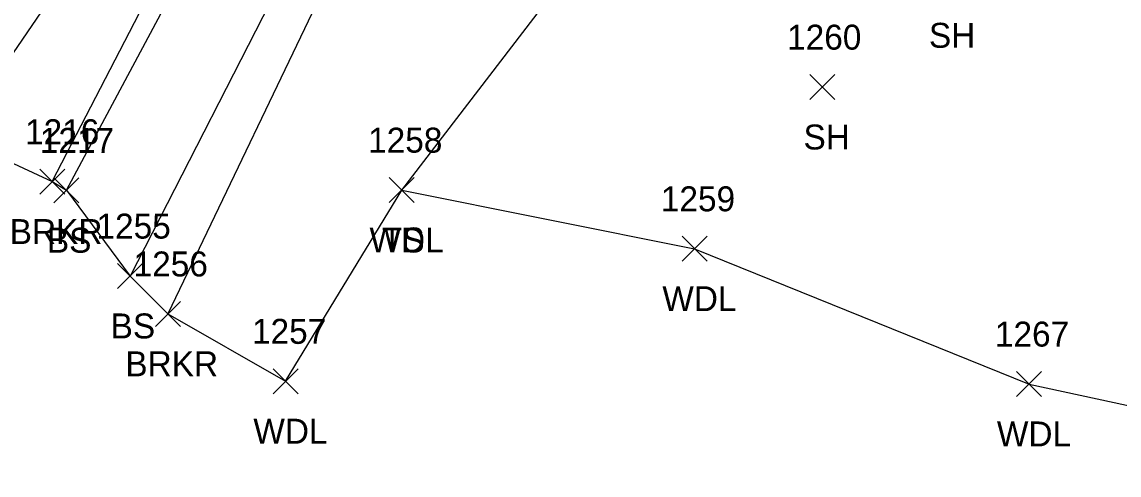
# Model space of a CAD drawing. Extents: x 1547013 to 1549434, y 267998 to 268739.
# Drawn here: x 1548511.9 to 1548599.8, y 268003.2 to 268039.5 of the extents above; entities that cross this region are included whole.
import ezdxf

# ---------------------------------------------------------------- set-up
doc = ezdxf.new("R2010")
doc.units = 0
for name, color, linetype in [('L_A', 7, 'Continuous'), ('L_I', 7, 'Continuous'), ('L_TIC', 7, 'Continuous'), ('LAWA', 7, 'Continuous'), ('LAWE', 7, 'Continuous'), ('LELB', 7, 'Continuous'), ('LSOGP', 7, 'Continuous')]:
    doc.layers.add(name, color=color, linetype=linetype)

msp = doc.modelspace()

# ---------------------------------------------------------------- linework, layer by layer
at = {"layer": 'L_TIC'}
for points in [[(1548575.003, 268033.257), (1548577.003, 268035.257)], [(1548577.003, 268033.257), (1548575.003, 268035.257)], [(1548513.299, 268025.679), (1548515.299, 268027.679)], [(1548515.299, 268025.679), (1548513.299, 268027.679)], [(1548514.429, 268024.988), (1548516.429, 268026.988)], [(1548516.429, 268024.988), (1548514.429, 268026.988)], [(1548541.298, 268025.004), (1548543.298, 268027.004)], [(1548543.298, 268025.004), (1548541.298, 268027.004)], [(1548541.298, 268025.004), (1548543.298, 268027.004)], [(1548543.298, 268025.004), (1548541.298, 268027.004)], [(1548564.761, 268020.303), (1548566.761, 268022.303)], [(1548566.761, 268020.303), (1548564.761, 268022.303)], [(1548519.536, 268018.117), (1548521.536, 268020.117)], [(1548521.536, 268018.117), (1548519.536, 268020.117)], [(1548522.564, 268015.083), (1548524.564, 268017.083)], [(1548524.564, 268015.083), (1548522.564, 268017.083)], [(1548531.993, 268009.684), (1548533.993, 268011.684)], [(1548533.993, 268009.684), (1548531.993, 268011.684)], [(1548591.567, 268009.464), (1548593.567, 268011.464)], [(1548593.567, 268009.464), (1548591.567, 268011.464)]]:
    msp.add_lwpolyline(points, dxfattribs=at)
at = {"layer": 'LAWA'}
msp.add_lwpolyline([(1548532.993, 268010.684), (1548542.298, 268026.004), (1548565.761, 268021.303), (1548592.567, 268010.464), (1548617.706, 268005.033), (1548639.26, 268030.863), (1548643.499, 268053.682), (1548616.029, 268059.847), (1548595.409, 268078.871)], dxfattribs=at)
at = {"layer": 'LAWE'}
for points in [[(1548514.299, 268026.679), (1548527.076, 268051.43), (1548534.81, 268069.637), (1548542.097, 268074.729), (1548548.832, 268079.869), (1548550.675, 268081.543)], [(1548555.64, 268077.538), (1548553.783, 268073.836), (1548551.667, 268067.092), (1548546.778, 268067.299), (1548543.997, 268065.954), (1548536.438, 268056.344), (1548537.305, 268044.796), (1548523.564, 268016.083)]]:
    msp.add_lwpolyline(points, dxfattribs=at)
at = {"layer": 'LELB'}
for points in [[(1548515.429, 268025.988), (1548528.703, 268050.828), (1548535.584, 268068.58), (1548541.29, 268072.138), (1548543.133, 268073.957), (1548550.63, 268078.711), (1548550.929, 268080.508), (1548553.575, 268079.042), (1548552.435, 268074.954), (1548545.979, 268069.28), (1548542.836, 268067.108), (1548534.631, 268056.786), (1548533.559, 268044.548), (1548520.536, 268019.117)], [(1548506.568, 268030.258), (1548522.561, 268053.685), (1548532.424, 268076.127), (1548533.489, 268078.219)], [(1548542.298, 268026.004), (1548559.928, 268048.986), (1548561.508, 268077.593)]]:
    msp.add_lwpolyline(points, dxfattribs=at)
at = {"layer": 'LSOGP'}
msp.add_lwpolyline([(1548448.226, 268090.845), (1548475.049, 268075.846), (1548475.605, 268055.115), (1548494.628, 268042.02), (1548506.568, 268030.258), (1548514.299, 268026.679), (1548515.429, 268025.988), (1548520.536, 268019.117), (1548523.564, 268016.083), (1548532.993, 268010.684), (1548542.298, 268026.004), (1548565.761, 268021.303), (1548592.567, 268010.464), (1548617.706, 268005.033), (1548631.114, 268003.169), (1548635.642, 268007.746), (1548640.169, 268012.324), (1548644.697, 268016.902), (1548649.224, 268021.48), (1548666.417, 268022.871), (1548707.907, 268010.051)], dxfattribs=at)

# ---------------------------------------------------------------- texts
at = {"layer": 'L_A'}
for s, p in [('SH', (1548584.54, 268037.405)), ('SH', (1548574.491, 268029.257)), ('BRKR', (1548510.89, 268021.679)), ('BS', (1548513.87, 268020.988)), ('WDL', (1548539.716, 268021.004)), ('TS', (1548540.708, 268021.004)), ('WDL', (1548563.178, 268016.303)), ('BS', (1548518.977, 268014.117)), ('BRKR', (1548520.154, 268011.083)), ('WDL', (1548530.411, 268005.684)), ('WDL', (1548589.985, 268005.464))]:
    msp.add_text(s, height=2, dxfattribs=at).set_placement(p)
at = {"layer": 'L_I'}
for s, p in [('1260', (1548573.176, 268037.257)), ('1216', (1548512.118, 268029.679)), ('1217', (1548513.304, 268028.988)), ('1258', (1548539.606, 268029.004)), ('1258', (1548539.606, 268029.004)), ('1259', (1548563.061, 268024.303)), ('1255', (1548517.843, 268022.117)), ('1256', (1548520.816, 268019.083)), ('1257', (1548530.301, 268013.684)), ('1267', (1548589.827, 268013.464))]:
    msp.add_text(s, height=2, dxfattribs=at).set_placement(p)

doc.saveas('drawing.dxf')
